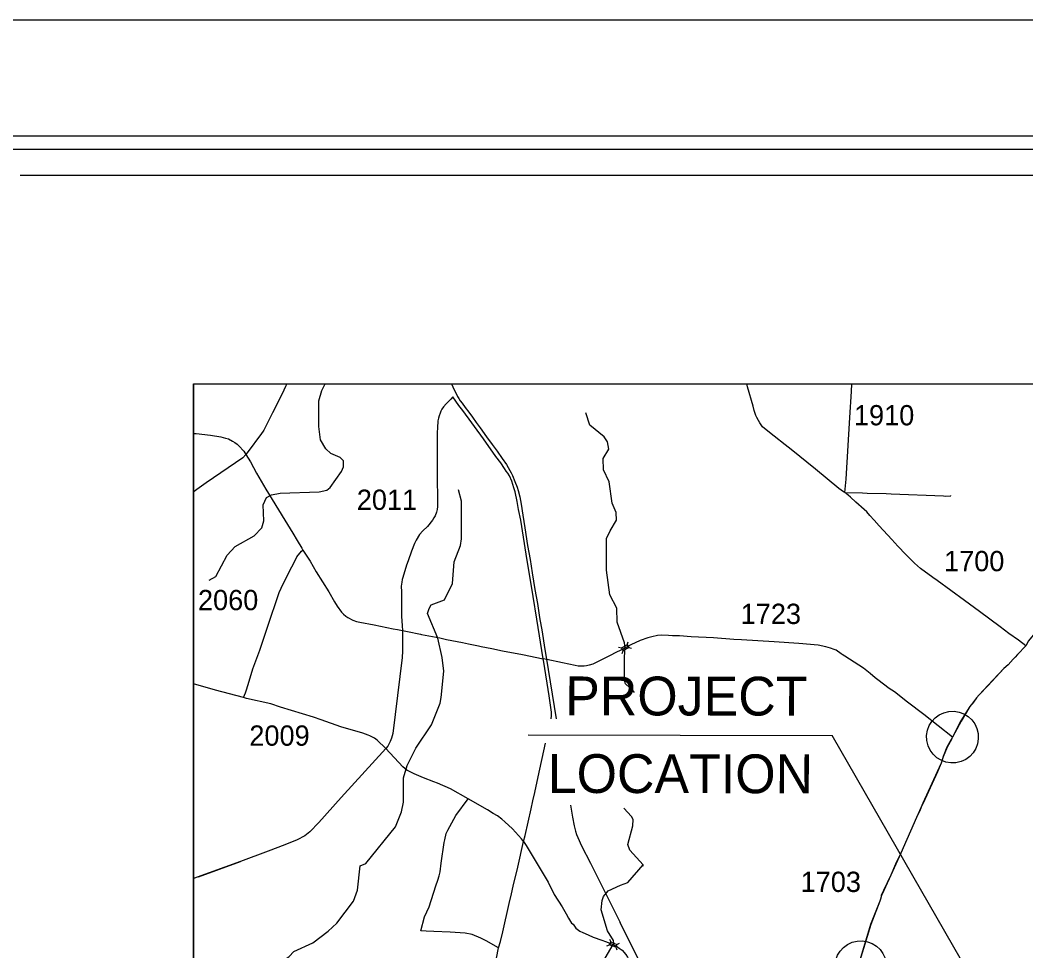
# Model space of a CAD drawing. Extents: x 0 to 2021, y 0 to 1321.
# Drawn here: x 278.5 to 511.8, y 1104.7 to 1320.6 of the extents above; entities that cross this region are included whole.
import ezdxf

# ---------------------------------------------------------------- set-up
doc = ezdxf.new("R2010")
doc.units = 0
for name, color, linetype in [('Default', 7, 'Continuous'), ('Dimension Lines', 7, 'Continuous'), ('Exist Hydro Stream or Body of Water', 7, 'Continuous'), ('Miscellaneous Lines', 7, 'Continuous'), ('Old_Level_26', 7, 'Continuous'), ('Scratch_Level_0', 7, 'Continuous'), ('Sheet Data Field CELL', 7, 'Continuous'), ('Sheet Plot Border Inside CELL', 7, 'Continuous'), ('Sheet Plot Border Outside CELL', 7, 'Continuous'), ('Sheet Title CELL', 7, 'Continuous'), ('Text', 7, 'Continuous')]:
    doc.layers.add(name, color=color, linetype=linetype)

msp = doc.modelspace()

# ---------------------------------------------------------------- linework, layer by layer
at = {"layer": 'Default'}
for p, q in [((419.32, 1175.71), (419.52, 1176.38)), ((417.31, 1175.16), (417.98, 1174.97)), ((418.14, 1173.67), (418.33, 1174.34)), ((419.66, 1175.1), (420.34, 1174.9)), ((414.57, 1105.86), (415.21, 1106.13)), ((415.22, 1107.44), (415.49, 1106.79)), ((416.9, 1106.2), (417.55, 1106.47)), ((416.63, 1105.56), (416.9, 1104.91))]:
    msp.add_line(p, q, dxfattribs=at)
for points in [[(399.79, 1172.48), (398.33, 1181.67), (397.45, 1186.9), (395.84, 1196.7), (394.62, 1204.62), (394.11, 1207.09), (393.76, 1208.99), (393.29, 1211.22), (393.04, 1212.15), (392.55, 1213.67), (391.96, 1214.92), (391.62, 1215.53), (391.25, 1215.99), (390.84, 1216.64), (389.97, 1217.9), (388.83, 1219.41), (385.96, 1223.5), (381.2, 1230.03), (380.27, 1231.24), (378.87, 1233.22)], [(540.37, 1210.37), (539.66, 1209.96), (538.83, 1209.39), (537.84, 1208.8), (536.06, 1207.58), (535.38, 1207.05), (534.26, 1205.77), (533.62, 1204.83), (533.1, 1203.9), (532.66, 1202.94), (532.29, 1201.77), (531.67, 1199.98), (531.33, 1199.31), (530.51, 1198.15), (529.25, 1196.75), (527.14, 1194.15), (524.68, 1191.22), (523.39, 1189.74), (521.63, 1187.64), (520.2, 1186.04), (512.44, 1176.63), (511.79, 1175.47)], [(401.65, 1158.55), (401.74, 1159.25), (401.76, 1160.12), (401.19, 1163.88), (399.93, 1171.67), (399.79, 1172.48)], [(395.24, 1130.06), (395.61, 1131.49), (397.04, 1137.64), (397.44, 1139.52), (397.86, 1141.43), (398.61, 1145.07), (400.32, 1152.92)], [(494.75, 1154.32), (494.71, 1154.24), (494.49, 1153.78), (493.48, 1151.96), (492.61, 1149.77), (492.14, 1148.24)], [(389.44, 1105.43), (389.92, 1106.9), (390.47, 1109.1), (391.94, 1115.66), (392.44, 1117.96), (392.84, 1119.75), (393.92, 1124.15), (395.24, 1130.06)], [(482.79, 1127.39), (481.56, 1124.85), (480.44, 1122.26), (478.8, 1118.75), (478.26, 1117.58), (478.14, 1116.96), (477.88, 1116.26), (475.76, 1110.83), (472.96, 1101.52)], [(388.26, 1099.46), (388.6, 1101.01), (389.44, 1105.43)]]:
    msp.add_lwpolyline(points, dxfattribs=at)
for points in [[(417.98, 1174.97), (419.32, 1175.71), (419.67, 1175.08), (418.33, 1174.34)], [(415.49, 1106.79), (416.9, 1106.21), (416.63, 1105.55), (415.21, 1106.13)]]:
    msp.add_lwpolyline(points, close=True, dxfattribs=at)
at = {"layer": 'Dimension Lines'}
for p in [(396.29, 1154.8), (507.84, 1083.41)]:
    msp.add_line(p, (466.85, 1154.69), dxfattribs=at)
at = {"layer": 'Exist Hydro Stream or Body of Water'}
msp.add_line((419.44, 1120.55), (422.98, 1124.7), dxfattribs=at)
for points in [[(418.71, 1172.89), (418.84, 1175.02), (418.69, 1176.13), (416.99, 1180.97), (416.9, 1184.19), (415.29, 1187.32), (414.51, 1193.05), (414.5, 1200.4), (415.34, 1202.18), (416.85, 1204.61), (416.76, 1206.4), (415.83, 1208.58), (415.13, 1213.55), (413.77, 1216.34), (413.76, 1218.96), (415.03, 1221.07), (414.77, 1222.77), (413.93, 1223.95), (410.63, 1226.64), (409.68, 1229.49)], [(376.41, 1172.76), (375.39, 1177.24), (373.01, 1182.97), (373.34, 1184.16), (373.84, 1184.98), (376.88, 1186.12), (378.81, 1189.9), (379.14, 1194.98), (380.65, 1198.77), (380.89, 1200.29), (380.87, 1209.07), (380.19, 1211.68)], [(357.39, 1124.45), (358.66, 1124.96), (365.55, 1133.49), (366.98, 1136.99), (367.4, 1139.24), (367.38, 1144.82), (368.23, 1147.7), (370.23, 1151.75), (373.93, 1157.16), (375.95, 1162.17), (376.11, 1163.49), (376.78, 1169.6), (376.41, 1172.76)], [(420.96, 1164.66), (420.77, 1164.97), (418.91, 1166.67), (418.66, 1167.4), (418.71, 1172.89)], [(423.04, 1124.32), (422.98, 1124.7), (419.94, 1128.08), (419.43, 1129.36), (420.6, 1133.75), (420.68, 1135.18), (420.34, 1135.85), (418.56, 1137.78)], [(331.34, 1080.81), (331.85, 1081.23), (337.05, 1092.66), (337.55, 1094.61), (338.04, 1100.92), (339.05, 1102.13), (340.91, 1103.38), (342, 1104.56), (346.38, 1106.6), (349.92, 1109.25), (351.94, 1111.1), (355.81, 1116.27), (356.73, 1118.78), (357.39, 1124.45)], [(413.12, 1101.13), (416.06, 1106.16), (416.18, 1106.53), (416.09, 1107.11), (414.75, 1109.34), (413.3, 1114.22), (413.47, 1116.42), (413.8, 1117.34), (414.9, 1118.61), (417.77, 1119.98), (419.44, 1120.55)]]:
    msp.add_lwpolyline(points, dxfattribs=at)
at = {"layer": 'Miscellaneous Lines'}
for points in [[(378.54, 1236.23), (378.86, 1235.55), (379.92, 1233.35), (380.22, 1232.86), (380.59, 1232.34), (381, 1231.77), (381.73, 1230.76), (382.56, 1229.67), (383.38, 1228.52), (384.25, 1227.32), (385.19, 1226.03), (386.69, 1223.95), (387.97, 1222.19), (389.11, 1220.63), (390.33, 1218.95), (391.33, 1217.51), (392.1, 1216.18), (392.41, 1215.61), (392.71, 1214.99), (393.24, 1213.63), (393.75, 1212.31), (394.02, 1211.48), (394.39, 1210.05), (394.67, 1208.32), (395.09, 1205.77), (395.54, 1202.82), (396.2, 1198.77), (396.76, 1195.51), (397.23, 1192.41), (397.91, 1188.52), (398.47, 1185.28), (398.98, 1182.08), (399.54, 1178.74), (400.09, 1175.05), (400.48, 1172.82), (402.83, 1158.54)], [(511.79, 1175.47), (509.85, 1173.5), (509.33, 1172.85), (508.86, 1172.4), (507.68, 1171.08), (506.68, 1170.19), (502.97, 1166.24), (500.93, 1164.14), (500.35, 1163.43), (499.5, 1162.22), (498.76, 1161.39), (496.73, 1158.04), (494.75, 1154.32)], [(511.8, 1175.47), (509.86, 1173.49), (509.35, 1172.84), (508.88, 1172.39), (507.69, 1171.07), (506.69, 1170.18), (502.99, 1166.23), (500.95, 1164.13), (500.37, 1163.42), (499.52, 1162.2), (498.78, 1161.37), (496.75, 1158.03), (494.77, 1154.3)], [(494.77, 1154.3), (494.73, 1154.23), (494.51, 1153.76), (493.5, 1151.95), (492.63, 1149.75), (492.16, 1148.23)], [(492.14, 1148.24), (491.24, 1146.25), (487.92, 1138.99), (487.66, 1138.43), (487.15, 1137.2), (486.43, 1135.66), (482.79, 1127.39)], [(492.16, 1148.23), (491.26, 1146.23), (487.95, 1138.98), (487.69, 1138.41), (487.17, 1137.18), (486.45, 1135.64), (482.82, 1127.37)], [(406.14, 1138.5), (406.64, 1135.69), (407.03, 1133.7), (407.22, 1132.81), (407.32, 1132.49), (407.54, 1131.73), (407.87, 1130.98), (408.74, 1129.1), (410.82, 1125.03), (417.66, 1111.25)], [(482.82, 1127.37), (481.6, 1124.83), (480.47, 1122.24), (478.83, 1118.73), (478.29, 1117.55), (478.17, 1116.94), (477.92, 1116.23), (475.8, 1110.81), (473, 1101.5)], [(426.8, 1093.06), (418.28, 1110), (417.66, 1111.25)]]:
    msp.add_lwpolyline(points, dxfattribs=at)
for centre in [(494.77, 1154.3), (473.48, 1101.04)]:
    msp.add_ellipse(centre, major_axis=(-0.81, 5.95), ratio=0.999692, dxfattribs=at)
at = {"layer": 'Old_Level_26'}
for points in [[(322.33, 1190.67), (323.85, 1191.53), (326.46, 1196.53), (328.39, 1198.55), (332.77, 1201.02), (334.55, 1202.88), (335.04, 1204.47), (334.86, 1208.19), (335.62, 1209.87), (336.8, 1210.48), (338.83, 1210.9), (347.85, 1211.18), (349.63, 1211.61), (350.39, 1212.19), (352.99, 1215.93), (353.5, 1217.02), (353.49, 1218.38), (352.73, 1219.13), (350.53, 1220.07), (349.35, 1221.16), (348.16, 1223.24), (347.73, 1226.38), (347.8, 1232.29), (348.47, 1234.74), (349.24, 1236.23)], [(340.33, 1236.23), (340.04, 1235.65), (339.23, 1233.93), (338.41, 1232.34), (337.68, 1230.82), (336.99, 1229.5), (336.25, 1227.96), (334.98, 1225.51), (334.33, 1224.51), (333.57, 1223.46), (332.03, 1221.47), (330.86, 1219.86)], [(469.77, 1211.03), (469.48, 1211.23), (468.38, 1211.95), (462.97, 1216.45), (457.33, 1221.04), (455.93, 1222.08), (453.42, 1224.11), (452.3, 1224.94), (450.71, 1226.3), (450.04, 1227.23), (449.73, 1227.78), (449.41, 1228.44), (449.18, 1228.87), (448.77, 1230.09), (448.52, 1231.1), (447.25, 1235.54), (447.03, 1236.23)], [(469.77, 1211.03), (470.1, 1214.12), (470.92, 1228.48), (471.33, 1234.49), (471.42, 1236.23)], [(378.87, 1233.22), (378.42, 1232.7), (378.06, 1232.39), (377.27, 1231.6), (376.68, 1230.93), (376.3, 1230.36), (376.1, 1229.95), (375.88, 1229.43), (375.7, 1228.84), (375.53, 1228.27), (375.39, 1227.64), (375.26, 1226.06), (375.2, 1224.97), (375.23, 1223.39), (375.18, 1218.48), (375.22, 1216.32), (375.23, 1214.11), (375.32, 1209.81), (375.29, 1207.81), (375.19, 1207.1), (375.05, 1206.49), (374.74, 1205.64), (374.46, 1205.17), (374.1, 1204.64), (373.01, 1203.18), (371.9, 1202.18), (371.11, 1201.29), (370.34, 1199.99), (369.96, 1199.22), (369.23, 1197.44), (368.51, 1195.23), (368.13, 1194.17), (367.23, 1191.33), (367.09, 1190.85), (366.99, 1190.24), (366.89, 1189.35), (366.91, 1187.97), (366.92, 1185.68), (366.96, 1184.12), (366.97, 1182.35), (367.12, 1180.11), (367.18, 1179.05)], [(318.71, 1224.7), (319.3, 1224.7), (322.65, 1224.31), (325.05, 1223.97), (326.13, 1223.62), (326.8, 1223.46), (327.77, 1222.99), (328.28, 1222.67), (328.79, 1222.29), (329.24, 1221.88), (330.37, 1220.63), (330.86, 1219.86)], [(330.86, 1219.86), (330.15, 1219.07), (321.64, 1213.27), (319.44, 1211.73), (318.85, 1211.28), (318.71, 1211.16)], [(330.86, 1219.86), (331.88, 1218.12), (333.3, 1215.51), (335.46, 1211.85), (339.88, 1204.65), (341.71, 1201.58), (342.77, 1199.9), (343.79, 1198.14), (344.07, 1197.64)], [(511.79, 1175.47), (510.11, 1176.75), (507.88, 1178.36), (505.87, 1179.9), (501.07, 1183.45), (498.7, 1185.12), (497.58, 1185.99), (491.19, 1190.62), (490.19, 1191.36), (487.33, 1193.42), (485.99, 1194.67), (483.98, 1196.67), (482.09, 1198.61), (480.73, 1200.13), (477.78, 1203.3), (476.6, 1204.66), (475.61, 1205.73), (474.87, 1206.56), (474.31, 1207.12), (472.34, 1208.8), (471.11, 1209.97), (470.6, 1210.44), (469.77, 1211.03)], [(469.77, 1211.03), (473.87, 1210.98), (474.99, 1210.91), (479.41, 1210.78), (480.51, 1210.7), (492.66, 1210.29), (493.25, 1210.23), (494.37, 1210.29), (494.39, 1210.32)], [(330.3, 1163.47), (330.54, 1164.06), (330.72, 1164.59), (330.92, 1165.04), (331.38, 1166.53), (332.47, 1170.16), (334.04, 1174.46), (335.21, 1177.91), (335.83, 1179.84), (338.56, 1187.83), (339.45, 1189.82), (341.52, 1193.78), (341.94, 1194.65), (342.69, 1196.09), (343.78, 1197.41), (344.07, 1197.64)], [(344.07, 1197.64), (344.36, 1197.17), (345.72, 1195.1), (347.16, 1192.64), (350.05, 1188), (351.4, 1185.66), (351.99, 1184.68), (353.02, 1183.31), (353.49, 1182.83), (354, 1182.38), (354.47, 1182.04), (355.62, 1181.43), (356.5, 1181.15), (357.31, 1180.97), (360.57, 1180.35), (364.97, 1179.45), (365.98, 1179.27), (367.18, 1179.05)], [(367.18, 1179.05), (367.2, 1177.6), (367.21, 1174.21), (367.1, 1172.79), (364.93, 1155.14), (364.65, 1154.09), (364.33, 1153.27), (363.8, 1152.21), (363.3, 1151.67)], [(367.18, 1179.05), (368.33, 1178.79), (371.33, 1178.17), (371.61, 1178.12), (375.82, 1177.3), (376.46, 1177.17), (377.42, 1176.98), (379.83, 1176.47), (381.08, 1176.23), (382.52, 1175.96), (384.01, 1175.64), (384.77, 1175.48), (385.45, 1175.35), (387.92, 1174.88), (390.37, 1174.35), (394.99, 1173.44), (399.79, 1172.48)], [(444.02, 1176.94), (439.3, 1177.36), (434.16, 1177.58), (431.46, 1177.8), (429.79, 1177.77), (428.85, 1177.85), (427.25, 1177.92), (426.36, 1177.87), (425.02, 1177.58), (424.1, 1177.34), (422.33, 1176.71), (420.16, 1175.7), (418.84, 1175.02)], [(476.85, 1168.05), (475.68, 1169.07), (474.09, 1170.28), (469.79, 1173.08), (469.21, 1173.46), (468.95, 1173.61), (467.8, 1174.44), (467.33, 1174.64), (466.5, 1174.96), (465.4, 1175.25), (463.61, 1175.62), (459.13, 1176), (453.39, 1176.38), (445.86, 1176.87), (444.02, 1176.94)], [(418.84, 1175.02), (418.14, 1174.63), (416.38, 1173.79), (415.64, 1173.42), (411.31, 1171.25), (410.49, 1170.98), (409.86, 1170.83), (409.35, 1170.76), (408.4, 1170.74), (407.91, 1170.79), (407.25, 1170.91), (404.28, 1171.52), (400.65, 1172.3), (399.79, 1172.48)], [(494.75, 1154.32), (488.12, 1159.57), (484.32, 1162.41), (481.29, 1164.8), (480.11, 1165.6), (477.42, 1167.56), (476.85, 1168.05)], [(330.3, 1163.47), (323.81, 1165.22), (318.71, 1166.67)], [(348.28, 1158.29), (346.53, 1158.92), (338.85, 1161.27), (336.61, 1162.02), (330.99, 1163.24), (330.3, 1163.47)], [(363.3, 1151.67), (361.31, 1153.58), (360.69, 1154.04), (359.63, 1154.6), (359.23, 1154.71), (357.94, 1155.18), (352.83, 1156.67), (348.28, 1158.29)], [(363.3, 1151.67), (352.93, 1140.29), (347.79, 1134.46), (345.7, 1132.31), (344.51, 1131.4), (342.77, 1130.43), (339.89, 1129.28), (335.97, 1127.87), (329.61, 1125.46), (319.84, 1121.85), (329.61, 1125.46), (318.71, 1121.46)], [(382.44, 1139.97), (378.3, 1142.26), (375.32, 1143.62), (374.47, 1143.92), (372.03, 1144.86), (369.89, 1145.79), (369.25, 1146.09), (368.19, 1146.66), (367.28, 1147.42), (363.3, 1151.67)], [(389.44, 1105.43), (386.6, 1107.04), (385.32, 1107.66), (383.3, 1108.52), (381.74, 1108.82), (378.25, 1109.04), (374.48, 1109.19), (372.68, 1109.24), (371.42, 1109.34), (372.31, 1112.62), (373.34, 1114.9), (374.9, 1119.78), (375.36, 1121.1), (375.66, 1122.13), (375.9, 1123.06), (376.15, 1125.02), (376.83, 1129.81), (376.99, 1130.49), (377.29, 1131.94), (377.72, 1132.68), (379.53, 1136.09), (382.44, 1139.97)], [(395.24, 1130.06), (394.75, 1130.7), (392.66, 1133.05), (390.91, 1134.65), (390.19, 1135.23), (389.18, 1136.01), (388.17, 1136.6), (386.89, 1137.41), (382.44, 1139.97)], [(395.24, 1130.06), (395.83, 1129.13), (400.95, 1120.63), (402.38, 1117.81), (404.23, 1114.96), (405.16, 1113.33), (405.67, 1112.32), (406.42, 1111.13), (406.73, 1110.88), (407.4, 1110), (408.28, 1109.24), (409, 1109), (410.21, 1108.4), (411.43, 1107.91), (413.4, 1107.22), (414.29, 1106.89), (416.06, 1106.16)], [(416.06, 1106.16), (416.83, 1105.81), (417.46, 1105.37), (418.11, 1104.84), (419.02, 1103.87), (419.38, 1103.24), (420.19, 1101.56), (423.04, 1097.17), (423.64, 1096.13), (424.96, 1093.48), (426.64, 1090.59), (428.28, 1087.66), (429.6, 1084.48), (430.19, 1083.4), (430.68, 1082.52), (431.22, 1081.69), (431.89, 1080.81), (432.13, 1080.54), (432.2, 1080.45)]]:
    msp.add_lwpolyline(points, dxfattribs=at)
at = {"layer": 'Scratch_Level_0'}
msp.add_lwpolyline([(318.71, 1236.23), (654.77, 1236.23), (654.77, 948.09), (318.71, 948.09)], close=True, dxfattribs=at)
at = {"layer": 'Sheet Plot Border Inside CELL'}
msp.add_lwpolyline([(15.6, 26.94), (2015.77, 26.94), (2015.77, 1293.68), (15.6, 1293.68)], close=True, dxfattribs=at)
at = {"layer": 'Sheet Plot Border Outside CELL'}
msp.add_lwpolyline([(2021.17, 1320.63), (0, 1320.63), (0, 0), (2021.17, 0)], close=True, dxfattribs=at)
at = {"layer": 'Sheet Title CELL'}
for q in [(318.71, 888.06), (654.77, 1236.23)]:
    msp.add_line((318.71, 1236.23), q, dxfattribs=at)
for points in [[(1988.78, 1290.62), (212.42, 1290.63)], [(1982.76, 1284.61), (278.47, 1284.61)]]:
    msp.add_lwpolyline(points, dxfattribs=at)

# ---------------------------------------------------------------- texts
at = {"layer": 'Sheet Data Field CELL'}
for s, p in [('PROJECT', (404.92, 1159.36)), ('LOCATION', (400.87, 1141.35))]:
    msp.add_text(s, height=9.004, rotation=359.915, dxfattribs=at).set_placement(p)
at = {"layer": 'Text'}
for s, p in [('1910', (471.91, 1226.62)), ('2011', (356.57, 1207.01)), ('1700', (492.81, 1192.78)), ('2060', (319.72, 1183.74)), ('1723', (445.63, 1180.54)), ('2009', (331.64, 1152.3)), ('1703', (459.54, 1118.37))]:
    msp.add_text(s, height=4.705, rotation=360, dxfattribs=at).set_placement(p)

doc.saveas('drawing.dxf')
